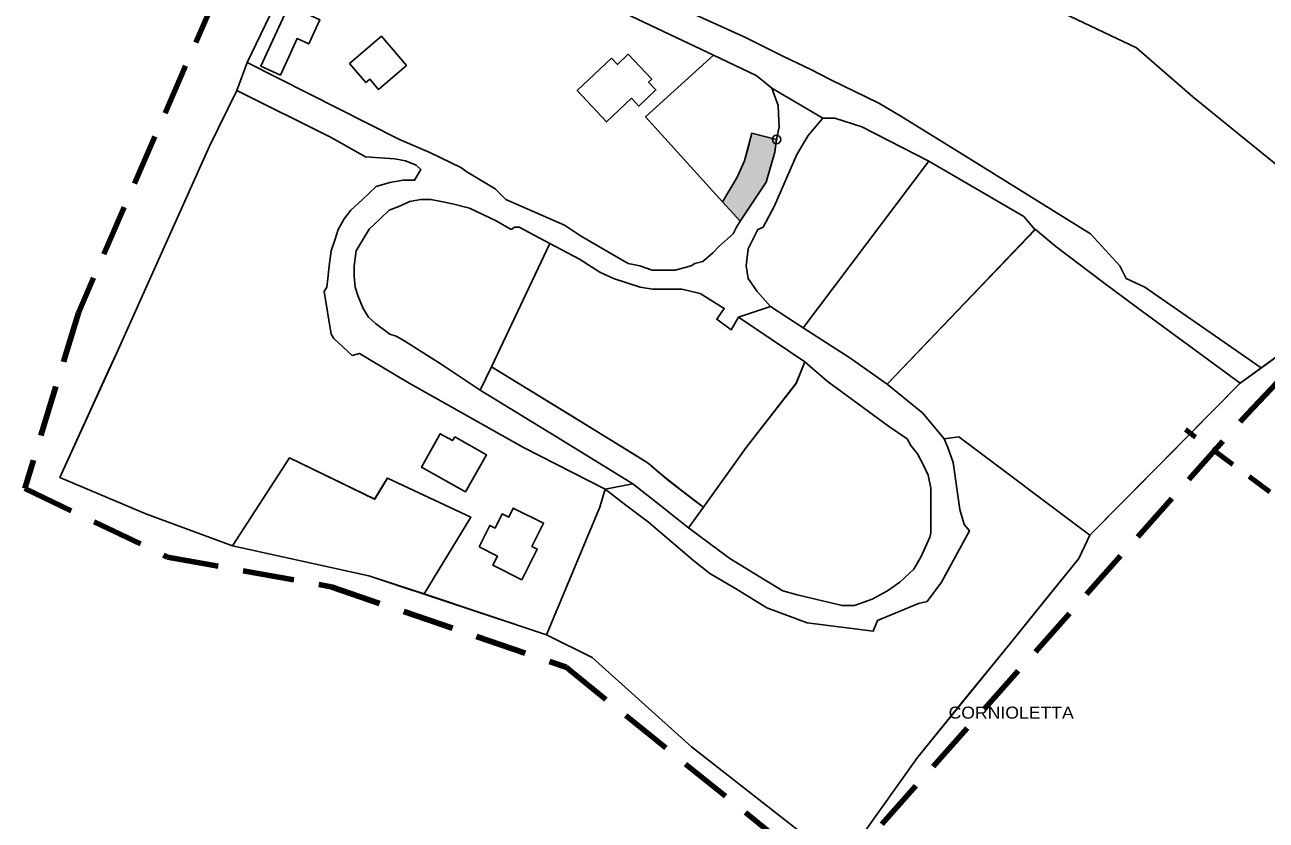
# Model space of a CAD drawing. Extents: x 654952 to 658955, y 890426 to 894481.
# Drawn here: x 657690.4 to 657981, y 893842.8 to 894028.8 of the extents above; entities that cross this region are included whole.
import ezdxf

# ---------------------------------------------------------------- set-up
doc = ezdxf.new("R2010")
doc.units = 0
doc.header["$LTSCALE"] = 4
doc.header["$PDMODE"] = 32
doc.header["$PDSIZE"] = 2
doc.linetypes.add('MEDIUM_DASHED', pattern=[4.5, 3, -1.5])
doc.linetypes.add('SHORT_DASHED', pattern=[2.7, 1.5, -1.2])
for name, color, linetype, lineweight in [('11', 7, 'Continuous', 25), ('13', 7, 'Continuous', 25), ('18', 7, 'Continuous', 25), ('19', 7, 'Continuous', 25), ('31', 7, 'Continuous', 25), ('35', 7, 'Continuous', 25), ('41', 7, 'SHORT_DASHED', 80), ('5', 7, 'Continuous', 25), ('6', 7, 'Continuous', 25), ('7', 7, 'MEDIUM_DASHED', 100), ('9', 7, 'Continuous', 25)]:
    doc.layers.add(name, color=color, linetype=linetype, lineweight=lineweight)
doc.layers.add('58', color=7, linetype='Continuous')

msp = doc.modelspace()

# ---------------------------------------------------------------- hatches: boundary and pattern name
at = {"layer": '18'}
msp.add_hatch(color=256, dxfattribs=at).paths.add_polyline_path([(657853.76, 893987.42), (657857.91, 893982.84), (657863.93, 893991.98), (657865.98, 893999.04), (657866.41, 894001.96), (657860.57, 894003.42), (657858.85, 893996.97), (657857.17, 893993.19)])

# ---------------------------------------------------------------- linework, layer by layer
at = {"layer": '11'}
for p, q in [((657742.51, 894019.94), (657740.02, 894013.44)), ((657865.26, 894013.94), (657877.25, 894006.93)), ((657865.01, 893962.93), (657857.5, 893960.44)), ((657974.89, 893944.94), (657979.85, 893948.55)), ((657826.31, 893920.17), (657832.74, 893921.43))]:
    msp.add_line(p, q, dxfattribs=at)
for points in [[(657952.62, 893967.44), (657979.85, 893948.55), (657994.86, 893959.44), (658007.24, 893972.94), (658005.62, 893974.44), (658004.36, 893972.94), (658003.12, 893974.44), (658002.71, 893973.96), (657994.24, 893980.94), (657997.74, 893984.44), (657963.86, 894011.94), (657950.62, 894023.44), (657927.49, 894034.44), (657911.62, 894044.94), (657896.36, 894051.44), (657887.99, 894054.94), (657875.74, 894061.44), (657878.86, 894067.92), (657833.36, 894083.94), (657828.12, 894085.94), (657823.74, 894087.44)], [(657846.74, 894031.44), (657858.99, 894025.94), (657867.86, 894021.44), (657874.24, 894018.44), (657879.12, 894015.94), (657890.36, 894010.44), (657895.49, 894007.44), (657911.62, 893997.44), (657931.19, 893985.31), (657939.86, 893979.94), (657946.74, 893972.44), (657948.24, 893969.44), (657952.62, 893967.44)]]:
    msp.add_lwpolyline(points, dxfattribs=at)
at = {"layer": '13'}
for p, q in [((657752.38, 893927.5), (657739.03, 893906.95)), ((657739.04, 893906.94), (657770.98, 893899.91))]:
    msp.add_line(p, q, dxfattribs=at)
for points in [[(657926.88, 893980.93), (657924.25, 893983.93), (657902.01, 893996.93), (657872.63, 893957.93)], [(657872.63, 893957.93), (657883.51, 893950.93), (657892.28, 893944.71), (657926.88, 893980.93)], [(657775.34, 893922.78), (657772.33, 893917.83), (657752.4, 893927.5)], [(657770.98, 893899.91), (657783.91, 893895.67), (657794.84, 893913.6), (657775.34, 893922.78)]]:
    msp.add_lwpolyline(points, dxfattribs=at)
at = {"layer": '18'}
for points in [[(657853.76, 893987.42), (657857.91, 893982.84), (657863.93, 893991.98), (657865.98, 893999.04), (657866.41, 894001.96), (657860.57, 894003.42), (657858.85, 893996.97), (657857.17, 893993.19)], [(657799.64, 893948.79), (657797.04, 893943.33), (657814.89, 893932.38), (657832.74, 893921.43), (657839.27, 893916.27), (657845.79, 893911.1), (657849.29, 893915.99), (657844.37, 893919.68), (657838.75, 893924.19), (657836.34, 893926.27), (657816.51, 893938.47)]]:
    msp.add_lwpolyline(points, close=True, dxfattribs=at)
at = {"layer": '19'}
msp.add_lwpolyline([(657860.57, 894003.42), (657859.96, 894000.97), (657858.85, 893996.97), (657857.17, 893993.19), (657853.76, 893987.42), (657835.75, 894007.29), (657851.67, 894021.72), (657861.64, 894016.94), (657863.51, 894015.44), (657865.26, 894013.94), (657866.76, 894009.94), (657866.88, 894007.94), (657867.01, 894004.94), (657866.41, 894001.96)], close=True, dxfattribs=at)
for points in [[(657813.34, 893977.63), (657799.64, 893948.79), (657833.38, 893928.15), (657836.34, 893926.27), (657841.15, 893922.11), (657847.59, 893917.25), (657849.28, 893915.98), (657859.25, 893929.94), (657871, 893944.94), (657873, 893949.94), (657857.5, 893960.44), (657855.75, 893957.44), (657852.38, 893959.94), (657854.13, 893962.44), (657848.5, 893965.94), (657844.25, 893966.94), (657837.37, 893966.94)], [(657837.38, 893966.94), (657834.5, 893967.44), (657828.25, 893969.44), (657825, 893970.94), (657820.25, 893973.94), (657813.34, 893977.63)]]:
    msp.add_lwpolyline(points, dxfattribs=at)
at = {"layer": '31'}
msp.add_lwpolyline([(657994.88, 893959.44), (657979.87, 893948.55), (657974.89, 893944.94), (657957.32, 893927.19), (657939.75, 893909.44), (657937.14, 893903.94), (657929.45, 893894.44), (657921.76, 893884.94), (657910.57, 893871.19), (657899.38, 893857.44), (657881.62, 893832.44)], dxfattribs=at)
at = {"layer": '35'}
for points in [[(657754.26, 894044.44), (657742.51, 894019.94), (657740.02, 894013.44), (657733.65, 894000.44), (657711.89, 893951.94), (657698.65, 893922.94)], [(657698.65, 893922.94), (657718.77, 893914.44), (657739.02, 893906.94), (657770.98, 893899.91), (657812.54, 893886.1), (657823.22, 893880.77), (657846.52, 893859.94), (657881.62, 893832.44), (657869.93, 893813.56), (657898.18, 893799.25), (657912.72, 893788.49), (657901.76, 893773.94), (657943.51, 893747.94), (658012.39, 893697.44), (658032.01, 893684.94)]]:
    msp.add_lwpolyline(points, dxfattribs=at)
at = {"layer": '41'}
msp.add_line((658086.27, 893842.76), (657962.08, 893934.12), dxfattribs=at)
at = {"layer": '5'}
for points in [[(657785.39, 894049.44), (657787.88, 894048.44), (657790.38, 894046.44), (657794.64, 894044.94), (657799.51, 894042.94), (657807.51, 894039.94), (657811.01, 894039.44), (657814.01, 894038.94), (657819.76, 894036.44), (657827.88, 894032.94), (657851.67, 894021.72), (657861.64, 894016.94), (657863.51, 894015.44), (657865.26, 894013.94), (657877.25, 894006.93)], [(657926.95, 893980.86), (657927.02, 893980.94), (657931.77, 893976.94), (657942.71, 893968.69), (657950.91, 893962.57), (657974.89, 893944.94), (657979.85, 893948.55), (657952.62, 893967.44), (657948.24, 893969.44), (657946.74, 893972.44), (657939.86, 893979.94), (657931.19, 893985.31), (657911.62, 893997.44), (657895.49, 894007.44), (657890.36, 894010.44), (657879.12, 894015.94), (657874.24, 894018.44), (657867.86, 894021.44), (657858.99, 894025.94), (657846.74, 894031.44)], [(657852.88, 893976.94), (657851.51, 893975.44), (657849.13, 893973.44), (657847.26, 893972.94), (657846.38, 893972.44), (657842.64, 893971.44), (657837.26, 893971.44), (657834.38, 893972.44), (657831.64, 893972.94), (657820.51, 893979.44), (657816.76, 893981.94), (657803.01, 893987.94), (657800.51, 893990.44), (657793.88, 893994.44), (657792.51, 893995.44), (657785.26, 893998.94), (657778.14, 894001.94), (657742.51, 894019.94), (657740.02, 894013.44), (657762.15, 894002.44), (657770.15, 893997.94)], [(657865.88, 893986.43), (657871.13, 893998.43), (657873.76, 894002.93), (657877.25, 894006.93), (657865.26, 894013.94), (657866.76, 894009.94), (657866.88, 894007.94), (657867.01, 894004.94), (657866.41, 894001.96)], [(657877.25, 894006.93), (657880.01, 894006.93), (657886.38, 894004.93), (657902.01, 893996.93)], [(657866.41, 894001.96), (657865.98, 893999.04), (657863.93, 893991.98), (657857.91, 893982.84), (657857.01, 893981.44), (657856.26, 893979.94), (657852.88, 893976.94)], [(657770.15, 893997.94), (657777.02, 893997.44), (657779.52, 893996.94), (657782.02, 893995.94), (657783.15, 893994.94), (657781.65, 893992.44), (657779.02, 893992.44), (657775.89, 893991.94), (657772.67, 893991)], [(657902.01, 893996.93), (657924.25, 893983.93), (657926.88, 893980.93)], [(657772.67, 893991), (657769.37, 893987.89), (657766.77, 893985.44)], [(657766.77, 893985.44), (657765.15, 893983.44), (657763.77, 893980.94), (657763.02, 893978.44), (657762.15, 893975.94), (657761.65, 893972.44), (657761.39, 893969.44), (657761.15, 893967.44), (657760.52, 893966.44), (657762.15, 893956.44), (657762.77, 893955.44), (657767.02, 893951.44), (657768.77, 893951.94), (657777.15, 893946.94), (657780.39, 893944.94), (657786.65, 893941.44), (657786.67, 893941.44), (657807.17, 893929.94), (657826.31, 893920.17), (657832.74, 893921.43)], [(657771.02, 893980.99), (657773.63, 893983.44), (657775.75, 893985.44), (657778.37, 893986.44), (657780.5, 893987.44), (657783.13, 893987.94), (657785.5, 893987.94)], [(657785.5, 893987.94), (657787.88, 893987.44), (657790.5, 893986.94), (657794.5, 893985.94), (657800.75, 893982.94), (657804.25, 893980.94), (657805.13, 893981.44), (657806.13, 893981.44), (657813.34, 893977.63), (657820.25, 893973.94), (657825, 893970.94), (657828.25, 893969.44), (657834.5, 893967.44), (657837.38, 893966.94), (657837.37, 893966.94), (657844.25, 893966.94), (657848.5, 893965.94), (657854.13, 893962.44), (657852.38, 893959.94), (657855.75, 893957.44), (657857.5, 893960.44), (657865.01, 893962.93)], [(657865.01, 893962.93), (657861.88, 893966.43), (657859.75, 893969.43), (657859.25, 893972.43), (657859.75, 893976.43), (657862.01, 893980.93), (657863.25, 893981.43), (657865.88, 893986.43)], [(657777.37, 893955.94), (657775.87, 893956.44), (657772.5, 893958.94), (657770.87, 893960.44), (657769.63, 893962.44), (657768.37, 893965.44), (657767.75, 893967.44), (657767.5, 893969.94), (657767.5, 893972.44), (657768, 893975.94), (657771.02, 893980.99)], [(657892.28, 893944.71), (657883.51, 893950.93), (657872.63, 893957.93), (657865.01, 893962.93), (657857.5, 893960.44), (657873, 893949.94)], [(657797.05, 893943.34), (657787.87, 893949.44), (657779.13, 893954.94), (657777.37, 893955.94)], [(657872.99, 893949.93), (657878.24, 893945.43), (657892.62, 893934.93)], [(657909.27, 893915.44), (657907.77, 893926.44), (657906.52, 893929.94), (657905.65, 893931.94), (657900.65, 893937.94), (657892.28, 893944.71)], [(657832.74, 893921.43), (657814.89, 893932.38), (657797.05, 893943.33)], [(657892.62, 893934.93), (657896.99, 893931.93), (657897.86, 893930.43), (657899.36, 893928.43), (657900.74, 893925.93), (657901.86, 893923.43), (657902.49, 893920.43), (657902.49, 893909.93)], [(657845.79, 893911.1), (657839.27, 893916.27), (657832.74, 893921.43), (657826.31, 893920.17)], [(657826.29, 893920.17), (657831.15, 893916.44), (657836.39, 893912.44), (657847.02, 893903.44), (657850.77, 893900.44), (657856.77, 893896.94), (657864.15, 893892.44), (657873.52, 893888.94), (657889.02, 893886.94), (657890.02, 893889.44), (657899.65, 893893.44), (657901.65, 893893.94), (657905.02, 893898.44), (657911.52, 893910.44), (657910.27, 893911.94), (657909.27, 893915.44)], [(657871.24, 893895.43), (657867.86, 893896.43), (657863.74, 893898.93), (657855.49, 893903.93), (657845.79, 893911.1)], [(657902.49, 893909.93), (657902.24, 893908.93), (657900.24, 893904.43), (657898.49, 893901.43), (657895.24, 893898.43), (657892.36, 893896.43), (657888.74, 893894.43), (657884.62, 893892.93), (657881.74, 893892.93), (657871.24, 893895.43)]]:
    msp.add_lwpolyline(points, dxfattribs=at)
msp.add_point((657866.41, 894001.96), dxfattribs=at)
at = {"layer": '6'}
for points in [[(657752.2, 894033.29), (657745.71, 894019.11), (657750.26, 894017.03), (657754.17, 894025.57), (657756.89, 894024.33), (657759.47, 894029.96)], [(657766.44, 894019.76), (657770.27, 894015.28), (657771.19, 894016.06), (657773.2, 894013.7), (657779.74, 894019.29), (657773.89, 894026.13)], [(657827.75, 894020.96), (657819.75, 894013.42), (657826.55, 894006.09), (657832.42, 894011.62), (657834.14, 894009.8), (657838.14, 894013.57), (657836.44, 894015.38), (657837.16, 894016.08), (657831.68, 894021.9), (657829.13, 894019.5)], [(657791.06, 893932.4), (657798.47, 893928.24), (657793.58, 893919.52), (657783.29, 893925.29), (657787.69, 893933.14), (657790.57, 893931.53)], [(657796.77, 893906.69), (657799.27, 893911.7), (657800.52, 893911.07), (657802.18, 893914.38), (657803.7, 893913.62), (657804.77, 893915.76), (657811.84, 893912.23), (657809.11, 893906.77), (657810.36, 893906.15), (657806.78, 893898.99), (657799.99, 893902.39), (657801.06, 893904.54)]]:
    msp.add_lwpolyline(points, close=True, dxfattribs=at)
at = {"layer": '7'}
msp.add_lwpolyline([(657749.6, 894068.69), (657702.96, 893961.43), (657690.43, 893920.33), (657723.85, 893904.31), (657762.13, 893897.35), (657817.12, 893878.54), (657879.07, 893828.4), (657976.52, 893937.75), (658007.85, 893970.48)], dxfattribs=at)
msp.add_lwpolyline([(657749.6, 894068.69), (657702.96, 893961.43), (657690.43, 893920.33), (657723.85, 893904.31), (657762.13, 893897.35), (657817.12, 893878.54), (657879.07, 893828.4), (657976.52, 893937.75), (658007.85, 893970.48)], dxfattribs=at)
at = {"layer": '9'}
for points in [[(657997.74, 893984.44), (657963.86, 894011.94), (657950.62, 894023.44), (657927.49, 894034.44), (657911.62, 894044.94), (657896.36, 894051.44), (657887.99, 894054.94), (657875.74, 894061.44), (657878.86, 894067.92), (657833.36, 894083.94), (657828.12, 894085.94), (657823.74, 894087.44)], [(657754.26, 894044.44), (657742.51, 894019.94), (657778.14, 894001.94), (657785.26, 893998.94), (657792.51, 893995.44), (657793.88, 893994.44), (657800.51, 893990.44), (657803.01, 893987.94), (657816.76, 893981.94), (657820.51, 893979.44), (657831.64, 893972.94), (657834.38, 893972.44), (657837.26, 893971.44), (657842.64, 893971.44), (657846.38, 893972.44)], [(657846.38, 893972.44), (657847.26, 893972.94), (657849.13, 893973.44), (657851.51, 893975.44), (657852.88, 893976.94), (657856.26, 893979.94), (657857.01, 893981.44), (657857.91, 893982.84), (657853.76, 893987.42), (657835.75, 894007.29), (657851.67, 894021.72), (657827.88, 894032.94), (657819.76, 894036.44), (657814.01, 894038.94), (657811.01, 894039.44), (657807.51, 894039.94), (657799.51, 894042.94)], [(657775.32, 893922.79), (657772.31, 893917.83), (657752.38, 893927.5), (657739.02, 893906.94), (657718.77, 893914.44), (657698.65, 893922.94), (657710.02, 893947.94), (657711.89, 893951.94), (657733.65, 894000.44), (657740.02, 894013.44), (657762.15, 894002.44), (657770.15, 893997.94)], [(657877.25, 894006.93), (657873.76, 894002.93), (657871.13, 893998.43), (657865.88, 893986.43), (657863.25, 893981.43)], [(657902.01, 893996.93), (657886.38, 894004.93), (657880.01, 894006.93), (657877.25, 894006.93)], [(657770.15, 893997.94), (657777.02, 893997.44), (657779.52, 893996.94), (657782.02, 893995.94), (657783.15, 893994.94), (657781.65, 893992.44), (657779.02, 893992.44), (657775.89, 893991.94), (657772.67, 893991)], [(657863.25, 893981.43), (657862.01, 893980.93), (657859.75, 893976.43), (657859.25, 893972.43), (657859.75, 893969.43), (657861.88, 893966.43), (657865.01, 893962.93), (657872.63, 893957.93), (657902.01, 893996.93)], [(657772.67, 893991), (657769.37, 893987.89), (657766.77, 893985.44)], [(657766.77, 893985.44), (657765.15, 893983.44), (657763.77, 893980.94), (657763.02, 893978.44), (657762.15, 893975.94), (657761.65, 893972.44), (657761.39, 893969.44), (657761.15, 893967.44), (657760.52, 893966.44), (657762.15, 893956.44), (657762.77, 893955.44), (657767.02, 893951.44), (657768.77, 893951.94), (657777.15, 893946.94), (657780.39, 893944.94), (657786.65, 893941.44)], [(657790.5, 893986.94), (657787.88, 893987.44), (657785.5, 893987.94), (657783.13, 893987.94), (657780.5, 893987.44), (657778.37, 893986.44), (657775.75, 893985.44), (657773.63, 893983.44), (657771.02, 893980.99), (657768, 893975.94)], [(657779.13, 893954.94), (657787.87, 893949.44), (657797.05, 893943.34), (657799.64, 893948.79), (657813.34, 893977.63), (657806.13, 893981.44), (657805.13, 893981.44), (657804.25, 893980.94), (657800.75, 893982.94), (657794.5, 893985.94), (657790.5, 893986.94)], [(657768, 893975.94), (657767.5, 893972.44), (657767.5, 893969.94), (657767.75, 893967.44), (657768.37, 893965.44), (657769.63, 893962.44), (657770.87, 893960.44), (657772.5, 893958.94), (657775.87, 893956.44), (657777.37, 893955.94), (657779.13, 893954.94)], [(657849.28, 893915.98), (657859.24, 893929.93), (657870.99, 893944.93), (657872.99, 893949.93), (657878.24, 893945.43)], [(657878.24, 893945.43), (657892.62, 893934.93), (657896.99, 893931.93), (657897.86, 893930.43), (657899.36, 893928.43), (657900.74, 893925.93), (657901.86, 893923.43), (657902.49, 893920.43), (657902.49, 893909.93)], [(657786.65, 893941.44), (657786.67, 893941.44), (657807.17, 893929.94), (657826.31, 893920.17), (657825.04, 893915.94), (657812.54, 893886.1), (657783.92, 893895.67), (657783.91, 893895.68), (657794.84, 893913.6), (657775.34, 893922.78), (657775.32, 893922.79)], [(657909.27, 893915.44), (657907.77, 893926.44), (657906.52, 893929.94), (657905.65, 893931.94), (657909.02, 893932.44), (657939.75, 893909.44), (657937.14, 893903.94), (657921.77, 893884.94), (657899.38, 893857.44), (657881.62, 893832.44), (657846.52, 893859.94)], [(657846.52, 893859.94), (657823.22, 893880.77), (657812.52, 893886.1), (657825.02, 893915.94), (657826.29, 893920.17)], [(657826.29, 893920.17), (657831.15, 893916.44), (657836.39, 893912.44), (657847.02, 893903.44), (657850.77, 893900.44), (657856.77, 893896.94), (657864.15, 893892.44), (657873.52, 893888.94), (657889.02, 893886.94), (657890.02, 893889.44), (657899.65, 893893.44), (657901.65, 893893.94), (657905.02, 893898.44), (657911.52, 893910.44), (657910.27, 893911.94), (657909.27, 893915.44)], [(657871.24, 893895.43), (657867.86, 893896.43), (657863.74, 893898.93), (657855.49, 893903.93), (657845.79, 893911.1), (657849.28, 893915.98)], [(657902.49, 893909.93), (657902.24, 893908.93), (657900.24, 893904.43), (657898.49, 893901.43), (657895.24, 893898.43), (657892.36, 893896.43), (657888.74, 893894.43), (657884.62, 893892.93), (657881.74, 893892.93), (657871.24, 893895.43)]]:
    msp.add_lwpolyline(points, dxfattribs=at)
msp.add_lwpolyline([(657892.28, 893944.71), (657927.02, 893980.94), (657931.77, 893976.94), (657942.71, 893968.69), (657950.91, 893962.57), (657974.89, 893944.94), (657939.75, 893909.44), (657909.02, 893932.44), (657905.65, 893931.94), (657900.65, 893937.94)], close=True, dxfattribs=at)

# ---------------------------------------------------------------- texts
at = {"layer": '58', "width": 1.1}
msp.add_text('CORNIOLETTA', height=2.801, dxfattribs=at).set_placement((657906.66, 893866.51))

doc.saveas('drawing.dxf')
